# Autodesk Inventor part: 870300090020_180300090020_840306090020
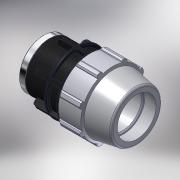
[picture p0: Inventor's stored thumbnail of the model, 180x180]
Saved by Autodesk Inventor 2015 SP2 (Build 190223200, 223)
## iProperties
Created: 2017-02
Part Number: 870300090020_180300090020_840306090020
Material: PVC-Piping
Description: PLASSON FEMALE ADAPTOR 90-2"
Document SubType Name: Modeling
Designer: KIM
Mass: 92.6774 g
Surface Area: 199.44 cm^2
Volume: 66.1981 cm^3
Density: 1.4 g/cm^3
Appearance: PTFE
Author: KIM
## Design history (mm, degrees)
derived "87030.ipt"
feature "Solid1::87030.ipt"
tag "TaggingFeature1"
body "Solid1"
other parameters: "d4" = 30.28571, "d5" = 53, "d7" = 152, "d9" = 30.28571, "d11" = 6.05714, "d12" = 121.6, "d13" = 120 deg, "d14" = 117, "d15" = 10 deg, "d16" = 136.8, "d18" = 4.5, "d19" = 35 deg, "d20" = 17.5 deg, "d21" = 141.36, "d23" = 0, "d25" = 360 deg, "d27" = 3.04, "d34" = 7.6, "d35" = 63.6, "d36" = 0, "d42" = 53, "d43" = 4.56, "d46" = 2.7, "d49" = 182, "d51" = 212, "d53" = 1.8, "d55" = 360 deg, "d62" = 72, "d63" = 56.656, "d64" = 70.66667, "d65" = 7.6, "d69" = 109.44, "d70" = 3.8, "d71" = 12.6, "d72" = 0.5, "d73" = 1, "E_" = 152, "H_" = 212, "l_" = 182, "Rp_Rc_" = 56.656
